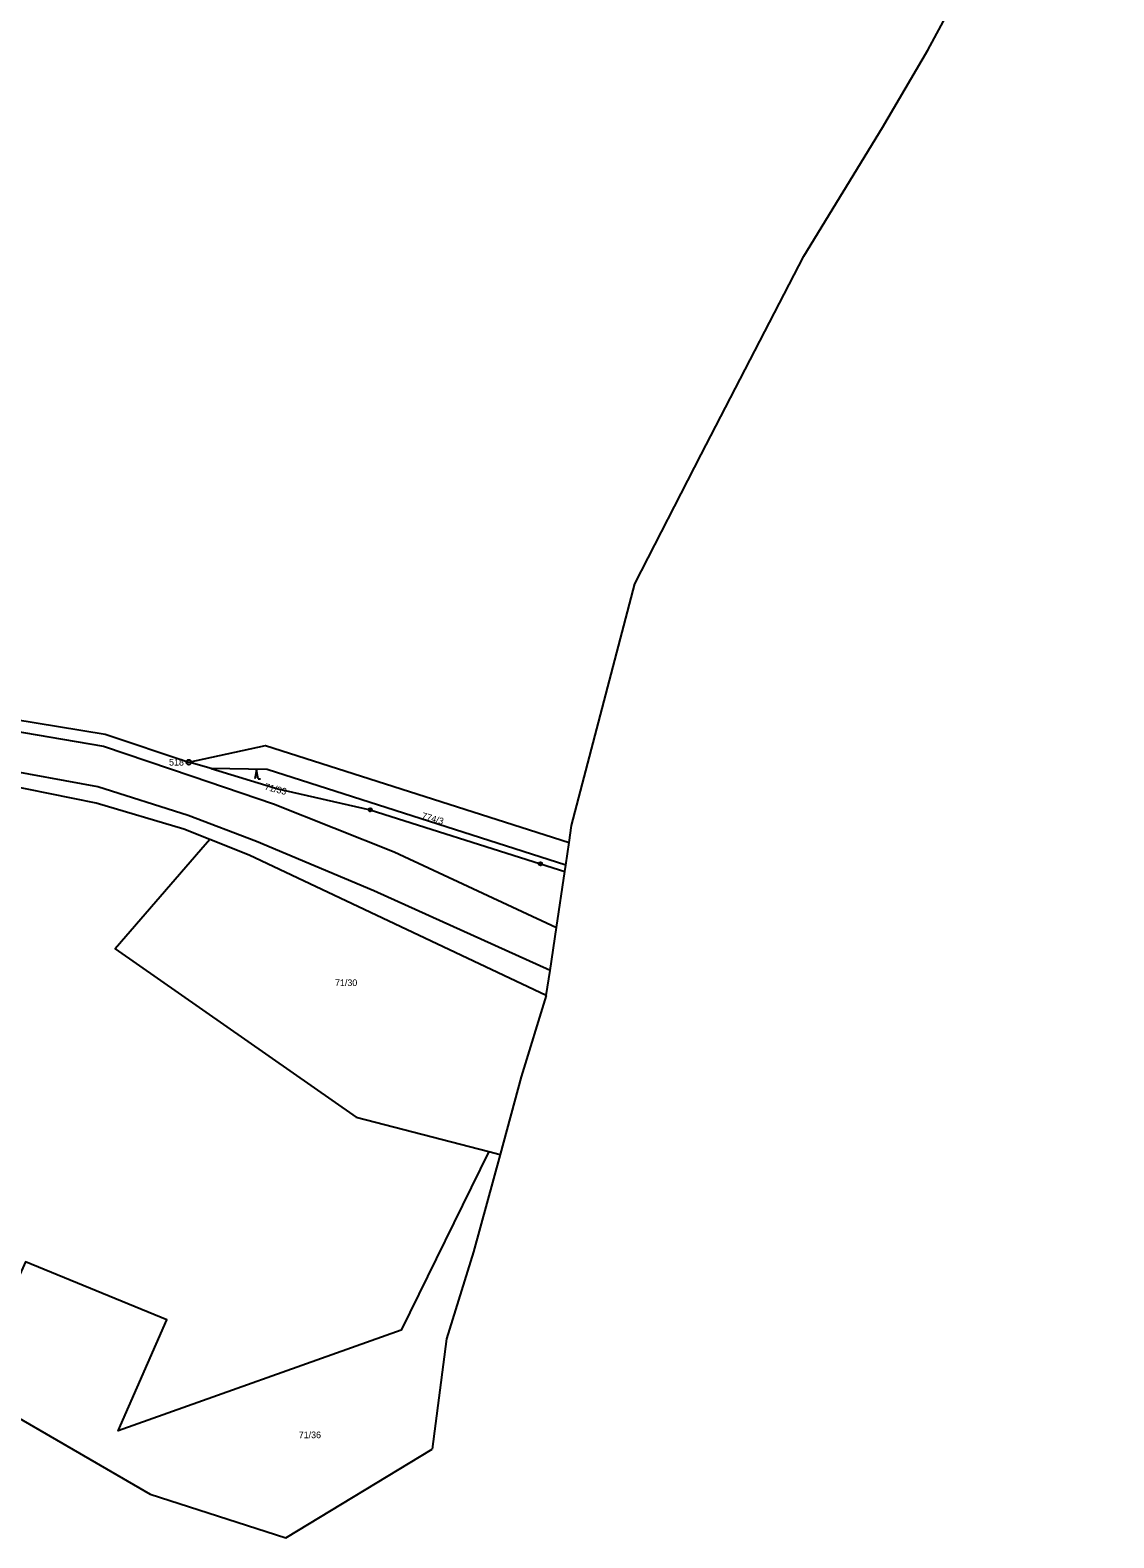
# Model space of a CAD drawing. Extents: x -745926 to -742978, y -968282 to -965689.
# Drawn here: x -743158.1 to -742995.1, y -967075 to -966848.3 of the extents above; entities that cross this region are included whole.
import ezdxf

# ---------------------------------------------------------------- set-up
doc = ezdxf.new("R2010")
doc.units = 0
for name, color, linetype in [('Hranice parcel', 7, 'Continuous'), ('Parcelní čísla', 7, 'Continuous'), ('Vnitřní kresba', 7, 'Continuous'), ('Značky bodu BP', 7, 'Continuous'), ('Značky kultur', 7, 'Continuous')]:
    doc.layers.add(name, color=color, linetype=linetype)

msp = doc.modelspace()

# ---------------------------------------------------------------- linework, layer by layer
at = {"layer": 'Hranice parcel'}
for p, q in [((-743130.84, -966959.35), (-743134.2, -966958.4)), ((-743077.53, -966973.88), (-743077.03, -966970.47)), ((-743078.91, -966983.26), (-743077.67, -966974.83)), ((-743077.67, -966974.83), (-743077.53, -966973.88)), ((-743079.86, -966989.69), (-743078.91, -966983.26)), ((-743080.47, -966993.48), (-743079.86, -966989.69)), ((-743089.1, -967016.92), (-743087.42, -967017.35)), ((-743167.17, -967052.69), (-743140, -967068.45)), ((-743119.6, -967075), (-743097.6, -967061.65)), ((-743140, -967068.45), (-743119.6, -967075))]:
    msp.add_line(p, q, dxfattribs=at)
for points in [[(-743077.03, -966970.47), (-743076.65, -966967.9), (-743067.16, -966931.57), (-743057.16, -966912.12), (-743041.76, -966882.3), (-743029.92, -966862.97), (-743023.11, -966851.33), (-743008.05, -966823.47), (-742995.12, -966809.06)], [(-743644.05, -967011.05), (-743635.15, -967008.49), (-743608.2, -966995.2), (-743596.11, -966987.66), (-743554.13, -966960.4), (-743526.49, -966945.06), (-743500.64, -966932.99), (-743485.78, -966925.55), (-743465.84, -966915.79), (-743445.79, -966903.57), (-743418.92, -966884.31), (-743389.08, -966865.49), (-743375.17, -966858.6), (-743367.56, -966856.27), (-743344.47, -966868.03), (-743323.78, -966879.63), (-743301.72, -966912.31), (-743278.8, -966926.17), (-743257.24, -966931.68), (-743245.35, -966936.01), (-743178.62, -966947.12), (-743164.23, -966951.34), (-743146.77, -966954.16), (-743134.2, -966958.4)], [(-743131.07, -966970.01), (-743134.97, -966968.44), (-743148.14, -966964.53), (-743165.46, -966961.06), (-743185.74, -966957.69), (-743231.4, -966949.66), (-743237.24, -966949.52)], [(-743134.2, -966958.4), (-743122.69, -966955.89), (-743077.03, -966970.47)], [(-743130.84, -966959.35), (-743120.81, -966962.4), (-743106.92, -966965.54), (-743081.35, -966973.67), (-743077.67, -966974.83)], [(-743077.53, -966973.88), (-743122.42, -966959.49), (-743130.84, -966959.35)], [(-743131.07, -966970.01), (-743132.4, -966971.55), (-743145.3, -966986.45), (-743109.05, -967011.75), (-743089.1, -967016.92)], [(-743080.47, -966993.48), (-743125.15, -966972.38), (-743131.07, -966970.01)], [(-743080.47, -966993.48), (-743084.26, -967005.68), (-743087.42, -967017.35)], [(-743089.1, -967016.92), (-743102.27, -967043.8), (-743144.85, -967058.9), (-743137.5, -967042.22), (-743158.75, -967033.5), (-743162.55, -967041.9)], [(-743087.42, -967017.35), (-743091.39, -967031.99), (-743095.48, -967045.08), (-743097.6, -967061.65)]]:
    msp.add_lwpolyline(points, dxfattribs=at)
at = {"layer": 'Vnitřní kresba'}
for p, q in [((-743164.42, -966953.03), (-743147.03, -966956.01)), ((-743147.03, -966956.01), (-743133.69, -966960.48)), ((-743147.89, -966962.12), (-743165.45, -966958.9)), ((-743134.31, -966966.42), (-743147.89, -966962.12)), ((-743133.69, -966960.48), (-743121.47, -966964.66)), ((-743124.02, -966970.34), (-743134.31, -966966.42)), ((-743121.47, -966964.66), (-743103.31, -966971.86)), ((-743106.41, -966977.72), (-743124.02, -966970.34)), ((-743103.31, -966971.86), (-743078.91, -966983.26)), ((-743079.86, -966989.69), (-743106.41, -966977.72))]:
    msp.add_line(p, q, dxfattribs=at)
at = {"layer": 'Značky bodu BP'}
for centre, radius in [((-743134.2, -966958.4), 0.375), ((-743134.2, -966958.4), 0.015), ((-743106.92, -966965.54), 0.25), ((-743106.92, -966965.54), 0.0152), ((-743081.35, -966973.67), 0.25), ((-743081.35, -966973.67), 0.0152)]:
    msp.add_circle(centre, radius, dxfattribs=at)
at = {"layer": 'Značky kultur'}
for p, q in [((-743124.02, -966959.57), (-743124.27, -966960.91)), ((-743123.77, -966960.91), (-743124.02, -966959.57)), ((-743123.77, -966960.91), (-743123.44, -966960.91))]:
    msp.add_line(p, q, dxfattribs=at)

# ---------------------------------------------------------------- texts
at = {"layer": 'Parcelní čísla'}
for s, rotation, p in [('71/33', 346, (-743122.9, -966962.52)), ('774/3', 344, (-743099.28, -966966.88))]:
    msp.add_text(s, height=1, rotation=rotation, dxfattribs=at).set_placement(p)
for s, p in [('71/30', (-743112.23, -966992.05)), ('71/36', (-743117.68, -967060.02))]:
    msp.add_text(s, height=1, dxfattribs=at).set_placement(p)
at = {"layer": 'Značky bodu BP'}
msp.add_text('518', height=1, dxfattribs=at).set_placement((-743137.18, -966958.9))

doc.saveas('drawing.dxf')
